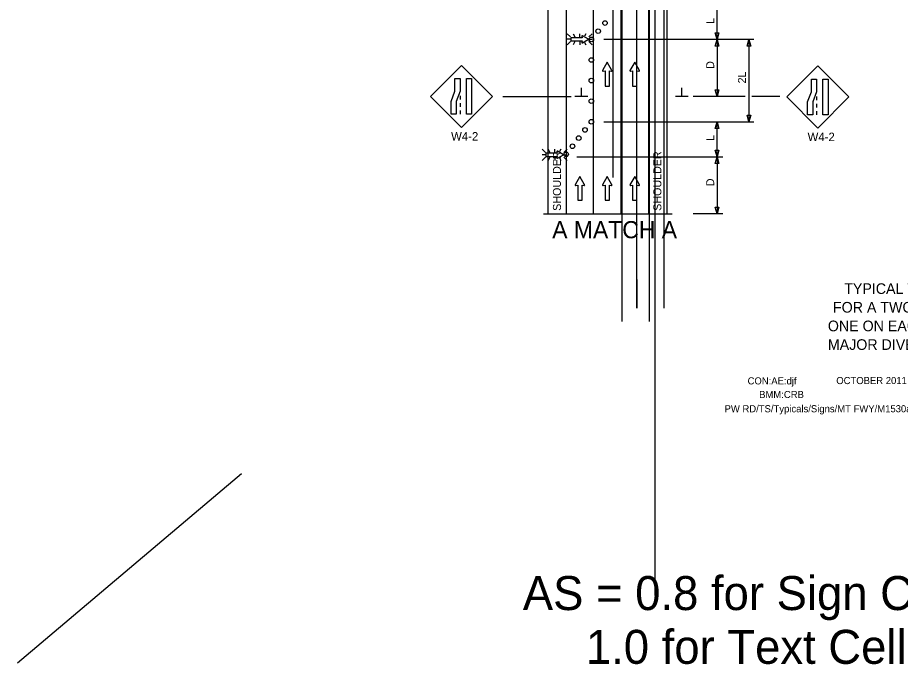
# Model space of a CAD drawing. Extents: x 16452 to 19508, y 5713 to 7079.
# Drawn here: x 16452 to 17224, y 5713 to 6279 of the extents above; entities that cross this region are included whole.
import ezdxf

# ---------------------------------------------------------------- set-up
doc = ezdxf.new("R2010")
doc.units = 0
for name, color, linetype in [('ALI_LEGAL_EX', 7, 'Continuous'), ('BORDER', 7, 'Continuous'), ('BORDER_SIGNAL_WO', 7, 'Continuous'), ('MT_SCRATCH_LEVEL_E', 7, 'Continuous'), ('PAVT_EDGE_EX', 7, 'Continuous'), ('TRAFFIC_SIGNS_PR', 7, 'Continuous'), ('TYPICAL_TEXT_DIMEN_PR', 7, 'Continuous')]:
    doc.layers.add(name, color=color, linetype=linetype)

msp = doc.modelspace()

# ---------------------------------------------------------------- linework, layer by layer
at = {"layer": 'ALI_LEGAL_EX'}
for p, q in [((16980.68, 6974.12), (16980.68, 6155.98)), ((17004.68, 6974.12), (17004.68, 6155.98)), ((16980.68, 6877.04), (16980.68, 6013.12)), ((17004.68, 6877.04), (17004.68, 6013.12)), ((16973.01, 6139.03), (16973.01, 6639.38)), ((16993.65, 6024.8), (16993.65, 6525.15)), ((17017.65, 6024.8), (17017.65, 6525.15)), ((16955.93, 6107.09), (16955.93, 6383.76)), ((16979.93, 6107.09), (16979.93, 6383.76)), ((17009.75, 5773.57), (17009.75, 6383.76))]:
    msp.add_line(p, q, dxfattribs=at)
for points in [[(16955.93, 6207.09), (16955.93, 6232.09)], [(16979.93, 6207.09), (16979.93, 6232.09)], [(16955.93, 6107.09), (16955.93, 6132.09)], [(16979.93, 6107.09), (16979.93, 6132.09)], [(16993.65, 6049.8), (16993.65, 6024.8)]]:
    msp.add_lwpolyline(points, dxfattribs=at)
at = {"layer": 'MT_SCRATCH_LEVEL_E'}
for p, q in [((16967.85, 6239.76), (16963.74, 6232.52)), ((16972, 6232.52), (16967.85, 6239.76)), ((16991.9, 6239.76), (16987.79, 6232.52)), ((16996.05, 6232.52), (16991.9, 6239.76)), ((16964.22, 6231.84), (16966, 6232.15)), ((16966, 6232.15), (16966, 6218.89)), ((16969.74, 6218.89), (16969.74, 6232.15)), ((16969.74, 6232.15), (16971.52, 6231.84)), ((16988.27, 6231.84), (16990.05, 6232.15)), ((16990.05, 6232.15), (16990.05, 6218.89)), ((16993.79, 6218.89), (16993.79, 6232.15)), ((16993.79, 6232.15), (16995.57, 6231.84)), ((16966, 6218.89), (16969.74, 6218.89)), ((16990.05, 6218.89), (16993.79, 6218.89)), ((16943.95, 6139.9), (16939.84, 6132.66)), ((16948.09, 6132.66), (16943.95, 6139.9)), ((16967.85, 6139.9), (16963.74, 6132.66)), ((16972, 6132.66), (16967.85, 6139.9)), ((16991.9, 6139.9), (16987.79, 6132.66)), ((16996.05, 6132.66), (16991.9, 6139.9)), ((16940.32, 6131.97), (16942.1, 6132.29)), ((16942.1, 6132.29), (16942.1, 6119.03)), ((16945.84, 6119.03), (16945.84, 6132.29)), ((16945.84, 6132.29), (16947.61, 6131.97)), ((16964.22, 6131.97), (16966, 6132.29)), ((16966, 6132.29), (16966, 6119.03)), ((16969.74, 6119.03), (16969.74, 6132.29)), ((16969.74, 6132.29), (16971.52, 6131.97)), ((16988.27, 6131.97), (16990.05, 6132.29)), ((16990.05, 6132.29), (16990.05, 6119.03)), ((16993.79, 6119.03), (16993.79, 6132.29)), ((16993.79, 6132.29), (16995.57, 6131.97)), ((16942.1, 6119.03), (16945.84, 6119.03)), ((16966, 6119.03), (16969.74, 6119.03)), ((16990.05, 6119.03), (16993.79, 6119.03))]:
    msp.add_line(p, q, dxfattribs=at)
for centre, start, end in [((16964.15, 6232.29), 150.42484, 279.96381), ((16971.59, 6232.29), 260.03619, 29.77312), ((16988.2, 6232.29), 150.42484, 279.96381), ((16995.64, 6232.29), 260.03619, 29.77312), ((16940.24, 6132.43), 150.42484, 279.96381), ((16947.68, 6132.43), 260.03619, 29.77312), ((16964.15, 6132.43), 150.42484, 279.96381), ((16971.59, 6132.43), 260.03619, 29.77312), ((16988.2, 6132.43), 150.42484, 279.96381), ((16995.64, 6132.43), 260.03619, 29.77312)]:
    msp.add_arc(centre, 0.463, start, end, dxfattribs=at)
at = {"layer": 'PAVT_EDGE_EX'}
for p, q in [((16915.93, 6383.76), (16915.93, 6107.09)), ((16931.93, 6383.76), (16931.93, 6107.09)), ((17003.93, 6383.76), (17003.93, 6107.09)), ((17019.93, 6383.76), (17019.93, 6107.09))]:
    msp.add_line(p, q, dxfattribs=at)
at = {"layer": 'TRAFFIC_SIGNS_PR'}
for p, q in [((16935.71, 6261.75), (16932.89, 6264.57)), ((16938, 6264.57), (16939.63, 6261.75)), ((16943.79, 6261.75), (16943.79, 6264.57)), ((16949.26, 6264.57), (16948.05, 6262.48)), ((16954.69, 6264.57), (16951.88, 6261.75)), ((16935.71, 6259.72), (16932.89, 6259.72)), ((16935.71, 6257.69), (16932.89, 6254.87)), ((16939.66, 6257.69), (16938.03, 6254.87)), ((16943.79, 6257.69), (16943.79, 6254.87)), ((16947.97, 6257.05), (16949.24, 6254.87)), ((16951.88, 6259.72), (16954.69, 6259.72)), ((16954.69, 6254.87), (16951.88, 6257.69)), ((16840.31, 6236.92), (16813.16, 6209.77)), ((16867.46, 6209.77), (16840.31, 6236.92)), ((17152.24, 6236.44), (17125.08, 6209.29)), ((17179.39, 6209.29), (17152.24, 6236.44)), ((16813.16, 6209.77), (16840.31, 6182.62)), ((16839.06, 6210.26), (16839.06, 6207.06)), ((16840.31, 6182.62), (16867.46, 6209.77)), ((17150.99, 6209.78), (17150.99, 6206.58)), ((16839.06, 6203.86), (16839.06, 6200.66)), ((17125.08, 6209.29), (17152.24, 6182.13)), ((17150.99, 6203.38), (17150.99, 6200.18)), ((17152.24, 6182.13), (17179.39, 6209.29)), ((16839.06, 6197.46), (16839.06, 6194.26)), ((17150.99, 6196.98), (17150.99, 6193.78)), ((16913.83, 6160.8), (16911.01, 6163.62)), ((16916.13, 6163.62), (16917.76, 6160.8)), ((16921.92, 6160.8), (16921.92, 6163.62)), ((16927.39, 6163.62), (16926.18, 6161.53)), ((16932.82, 6163.62), (16930, 6160.8)), ((16913.83, 6158.77), (16911.01, 6158.77)), ((16913.83, 6156.74), (16911.01, 6153.92)), ((16917.78, 6156.74), (16916.15, 6153.92)), ((16921.92, 6156.74), (16921.92, 6153.92)), ((16926.1, 6156.1), (16927.36, 6153.92)), ((16930, 6158.77), (16932.82, 6158.77)), ((16932.82, 6153.92), (16930, 6156.74))]:
    msp.add_line(p, q, dxfattribs=at)
for points in [[(16945.62, 6262.4), (16945.85, 6261.11), (16936.12, 6261.11), (16936.12, 6258.36), (16945.85, 6258.36), (16945.62, 6257.06)], [(16946.12, 6256.71), (16951.43, 6259.72), (16946.12, 6262.76)], [(16923.74, 6161.45), (16923.97, 6160.15), (16914.25, 6160.15), (16914.25, 6157.41), (16923.97, 6157.41), (16923.74, 6156.11)], [(16924.24, 6155.75), (16929.55, 6158.77), (16924.24, 6161.81)]]:
    msp.add_lwpolyline(points, dxfattribs=at)
for points in [[(16839.06, 6225.5), (16839.06, 6214.32), (16835.72, 6205.44), (16835.72, 6194.26), (16831.22, 6194.26), (16831.22, 6205.44), (16834.57, 6214.32), (16834.57, 6225.5)], [(16849.2, 6225.5), (16849.2, 6194.26), (16844.7, 6194.26), (16844.7, 6225.5)], [(17150.99, 6225.02), (17150.99, 6213.84), (17147.65, 6204.96), (17147.65, 6193.78), (17143.15, 6193.78), (17143.15, 6204.96), (17146.5, 6213.84), (17146.5, 6225.02)], [(17161.13, 6225.02), (17161.13, 6193.78), (17156.63, 6193.78), (17156.63, 6225.02)]]:
    msp.add_lwpolyline(points, close=True, dxfattribs=at)
for centre in [(16965.93, 6273.93), (16959.93, 6266.79), (16953.93, 6259.65), (16953.93, 6241.65), (16953.93, 6223.65), (16953.93, 6205.65), (16953.93, 6187.65), (16948.43, 6180.52), (16942.94, 6173.39), (16937.44, 6166.26), (16931.94, 6159.14)]:
    msp.add_circle(centre, 2, dxfattribs=at)
for centre, start, end in [((16945.95, 6262.46), 61.48329, 189.95933), ((16945.95, 6257.01), 170.73078, 298.89165), ((16924.08, 6161.51), 61.48329, 189.95933), ((16924.08, 6156.05), 170.73078, 298.89165)]:
    msp.add_arc(centre, 0.341, start, end, dxfattribs=at)
at = {"layer": 'TYPICAL_TEXT_DIMEN_PR'}
for p, q in [((17064.03, 6259.65), (17064.03, 6288.21)), ((17064.03, 6259.65), (17062.46, 6265.51)), ((17062.46, 6265.51), (17064.03, 6265.51)), ((17064.03, 6265.51), (17065.6, 6265.51)), ((17065.6, 6265.51), (17064.03, 6259.65)), ((17096.07, 6259.65), (16964.93, 6259.65)), ((17062.46, 6253.79), (17064.03, 6259.65)), ((17064.03, 6259.65), (17064.03, 6209.65)), ((17064.03, 6259.65), (17065.6, 6253.79)), ((17090.26, 6253.79), (17091.83, 6259.65)), ((17091.83, 6259.65), (17093.4, 6253.79)), ((17091.83, 6259.65), (17091.83, 6187.65)), ((17064.03, 6253.79), (17062.46, 6253.79)), ((17065.6, 6253.79), (17064.03, 6253.79)), ((17091.83, 6253.79), (17090.26, 6253.79)), ((17093.4, 6253.79), (17091.83, 6253.79)), ((16945.22, 6209.65), (16945.22, 6217.44)), ((17033.15, 6209.65), (17033.15, 6217.44)), ((16876.41, 6209.65), (16936.23, 6209.65)), ((16950.84, 6209.65), (16939.59, 6209.65)), ((17038.78, 6209.65), (17027.53, 6209.65)), ((17088.65, 6209.65), (17043.03, 6209.65)), ((17064.03, 6209.65), (17062.46, 6215.51)), ((17062.46, 6215.51), (17064.03, 6215.51)), ((17064.03, 6215.51), (17065.6, 6215.51)), ((17065.6, 6215.51), (17064.03, 6209.65)), ((17118.85, 6209.65), (17094.37, 6209.65)), ((16964.93, 6187.65), (17096.07, 6187.65)), ((17062.46, 6181.79), (17064.03, 6187.65)), ((17064.03, 6157.09), (17064.03, 6187.65)), ((17064.03, 6187.65), (17065.6, 6181.79)), ((17091.83, 6187.65), (17090.26, 6193.51)), ((17090.26, 6193.51), (17091.83, 6193.51)), ((17091.83, 6193.51), (17093.4, 6193.51)), ((17093.4, 6193.51), (17091.83, 6187.65)), ((17064.03, 6181.79), (17062.46, 6181.79)), ((17065.6, 6181.79), (17064.03, 6181.79)), ((16941.19, 6157.09), (17069.03, 6157.09)), ((17064.03, 6157.09), (17062.46, 6162.95)), ((17062.46, 6162.95), (17064.03, 6162.95)), ((17062.46, 6151.22), (17064.03, 6157.09)), ((17064.03, 6162.95), (17065.6, 6162.95)), ((17065.6, 6162.95), (17064.03, 6157.09)), ((17064.03, 6157.09), (17064.03, 6107.09)), ((17064.03, 6157.09), (17065.6, 6151.22)), ((17064.03, 6151.22), (17062.46, 6151.22)), ((17065.6, 6151.22), (17064.03, 6151.22)), ((17064.03, 6107.09), (17062.46, 6112.95)), ((17062.46, 6112.95), (17064.03, 6112.95)), ((17064.03, 6112.95), (17065.6, 6112.95)), ((17065.6, 6112.95), (17064.03, 6107.09)), ((16912, 6107.09), (17024.65, 6107.09)), ((17069.03, 6107.09), (17043.03, 6107.09)), ((16647.75, 5880), (16452.02, 5714.53))]:
    msp.add_line(p, q, dxfattribs=at)

# ---------------------------------------------------------------- texts
at = {"layer": 'BORDER'}
for s, p in [('TYPICAL TEMPORARY TRAFFIC CONTROL', (17175.21, 6037.14)), ('FOR A TWO-LANE CLOSURE ON A FREEWAY,', (17165.41, 6020.84)), ('ONE ON EACH SIDE OF A GORE AREA AT A ', (17160.92, 6004.54)), ('MAJOR DIVERGENCE USING A SINGLE STEP ', (17160.92, 5988.24))]:
    msp.add_text(s, height=9.3, dxfattribs=at).set_placement(p)
at = {"layer": 'BORDER_SIGNAL_WO'}
for s, height, p in [('CON:AE:djf  ', 6.2, (17090.69, 5958.06)), ('    OCTOBER 2011    ', 6.2, (17159.08, 5958.34)), ('BMM:CRB   ', 6.2, (17100.81, 5946.17)), ('PW RD/TS/Typicals/Signs/MT FWY/M1530a.dgn      ', 6.2, (17070.55, 5933.71)), ('AS = 0.8 for Sign Cells', 29.7271, (16894.01, 5760.83)), ('     1.0 for Text Cells', 29.7271, (16894.01, 5713.82))]:
    msp.add_text(s, height=height, dxfattribs=at).set_placement(p)
at = {"layer": 'TRAFFIC_SIGNS_PR'}
for p in [(16831.27, 6171.18), (17143.2, 6170.69)]:
    msp.add_text('W4-2', height=7.44, dxfattribs=at).set_placement(p)
at = {"layer": 'TYPICAL_TEXT_DIMEN_PR'}
for s, p in [('L', (17061.56, 6273.29)), ('D', (17061.47, 6233.87)), ('2L', (17089.28, 6221.15)), ('L', (17061.47, 6170.94)), ('SHOULDER', (16927.37, 6109.79)), ('SHOULDER', (17015.23, 6109.79)), ('D', (17061.47, 6131.3))]:
    msp.add_text(s, height=7, rotation=90, dxfattribs=at).set_placement(p)
msp.add_text('A MATCH A', height=15, dxfattribs=at).set_placement((16919.74, 6085.81))

doc.saveas('drawing.dxf')
